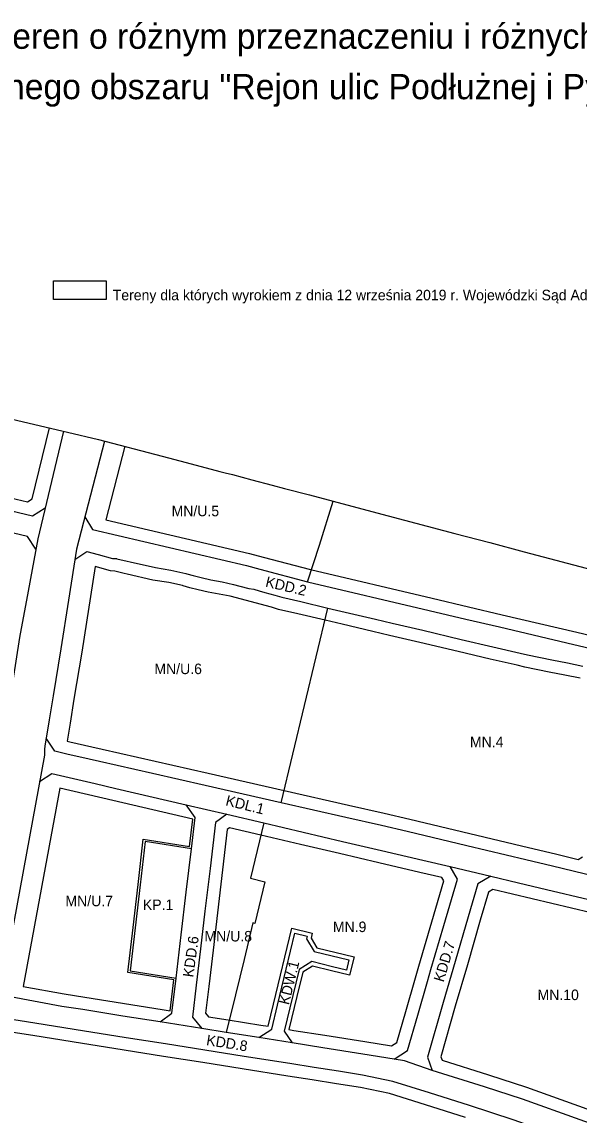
# Model space of a CAD drawing. Extents: x 7416945 to 7418410, y 5548550 to 5549803.
# Drawn here: x 7417613 to 7417879, y 5549282 to 5549803 of the extents above; entities that cross this region are included whole.
import ezdxf

# ---------------------------------------------------------------- set-up
doc = ezdxf.new("R2010")
doc.units = 0
for name, color, linetype in [('_LEGENDA_opisy', 7, 'Continuous'), ('info', 7, 'Continuous'), ('linie rozgraniczające', 7, 'Continuous'), ('nieprzekraczalne linie zabudowy', 7, 'Continuous'), ('obowiazujace linie zabudowy', 7, 'Continuous'), ('przeznaczenia terenów', 7, 'Continuous'), ('wyrok sądu', 7, 'Continuous')]:
    doc.layers.add(name, color=color, linetype=linetype)

msp = doc.modelspace()

# ---------------------------------------------------------------- linework, layer by layer
at = {"layer": 'linie rozgraniczające'}
for points in [[(7417590.76, 5549617.84), (7417614.12, 5549612.32), (7417635.08, 5549607.36), (7417649.74, 5549603.95), (7417680.13, 5549595.95), (7417691.64, 5549592.93), (7417707.71, 5549588.7), (7417710.12, 5549588.07), (7417713.61, 5549587.15), (7417718.26, 5549585.93), (7417722.94, 5549584.69), (7417732.53, 5549582.17), (7417738.47, 5549580.61), (7417750.37, 5549577.48), (7417761.66, 5549574.53), (7417782.44, 5549569.02), (7417819.55, 5549559.17), (7417836.24, 5549554.75), (7417852.72, 5549550.37), (7417888.31, 5549540.93)], [(7417619.99, 5549551.6), (7417616.03, 5549557.7), (7417598.58, 5549561.83), (7417597.44, 5549562.11), (7417575.89, 5549566.8), (7417573.85, 5549567.3), (7417560.72, 5549570.46), (7417545.86, 5549574.04), (7417545.19, 5549574.21), (7417538.59, 5549575.77), (7417490.83, 5549587.31), (7417457.88, 5549595), (7417445.43, 5549597.84), (7417449.35, 5549610.27)], [(7417624.4, 5549571.14), (7417618.37, 5549567.42), (7417600.92, 5549571.55), (7417599.7, 5549571.85), (7417578.14, 5549576.54), (7417576.21, 5549577.02), (7417563.06, 5549580.18), (7417548.26, 5549583.75), (7417547.57, 5549583.92), (7417540.91, 5549585.5), (7417493.14, 5549597.04), (7417461.13, 5549604.52), (7417462.02, 5549607.14), (7417449.35, 5549610.27)], [(7417633.2, 5549607.8), (7417620.9, 5549556.55), (7417616.31, 5549531.69), (7417612.22, 5549509.52), (7417608.98, 5549489.09), (7417604.95, 5549463.66), (7417603.56, 5549458.92), (7417602.9, 5549456.68), (7417600.38, 5549448.11)], [(7417652.74, 5549603.16), (7417639.38, 5549551.6), (7417635.56, 5549527.28), (7417631.94, 5549504.23), (7417628.25, 5549481.74), (7417626.38, 5549470.4), (7417624.29, 5549457.71), (7417624.07, 5549456.36), (7417624.04, 5549453.54), (7417603.72, 5549342.84), (7417602.77, 5549338.52), (7417599.85, 5549325.25), (7417588.8, 5549282.89), (7417582.37, 5549257.96)], [(7417749.47, 5549536.13), (7417755.05, 5549553.61), (7417761.66, 5549574.53)], [(7417643.37, 5549567), (7417646.98, 5549561.01), (7417720.34, 5549543.79), (7417726.77, 5549542.1), (7417749.34, 5549536.16), (7417749.47, 5549536.13), (7417807.39, 5549522.48), (7417824.82, 5549518.37), (7417840.84, 5549514.6), (7417876.37, 5549506.27), (7417906.25, 5549499.17)], [(7417638.6, 5549546.65), (7417644.26, 5549550.46), (7417649.73, 5549549.18), (7417656.46, 5549547.23), (7417658.4, 5549547.16), (7417658.59, 5549547.12), (7417663.48, 5549545.97), (7417664.88, 5549545.65), (7417676.93, 5549542.84), (7417684.36, 5549541.59), (7417691.39, 5549540.13), (7417691.91, 5549539.95), (7417694.87, 5549539.08), (7417698.73, 5549538.09), (7417703.28, 5549537.05), (7417708.67, 5549536.04), (7417714.16, 5549534.74), (7417717.21, 5549534.01), (7417721.4, 5549532.94), (7417723.87, 5549532.52), (7417726.45, 5549531.79), (7417729.02, 5549531.07), (7417731.46, 5549530.42), (7417733.91, 5549529.78), (7417737.21, 5549528.77), (7417746.22, 5549526.65), (7417759.16, 5549523.61), (7417767.29, 5549521.69), (7417781.87, 5549518.26), (7417789.8, 5549516.4), (7417804.3, 5549512.99), (7417822.59, 5549508.68), (7417837.75, 5549505.15), (7417850.7, 5549502.15), (7417854.27, 5549501.33), (7417865.79, 5549498.98), (7417873.31, 5549497.54), (7417880.65, 5549495.98)], [(7417736.94, 5549430.77), (7417759.16, 5549523.61)], [(7417886.55, 5549395.7), (7417866.12, 5549400.6), (7417853.4, 5549403.64), (7417825.31, 5549410.36), (7417796.84, 5549417.18), (7417784.66, 5549419.94), (7417767.63, 5549423.81), (7417752.29, 5549427.29), (7417736.94, 5549430.77), (7417718.83, 5549434.88), (7417700.71, 5549439), (7417675.49, 5549444.73), (7417650.26, 5549450.45), (7417645.37, 5549451.55), (7417634.72, 5549453.96), (7417629.06, 5549455.36), (7417624.93, 5549461.54)], [(7417621.74, 5549441), (7417627.52, 5549444.78), (7417648.26, 5549439.96), (7417658.02, 5549437.69), (7417691.54, 5549429.86), (7417711.02, 5549425.31), (7417728.62, 5549421.18), (7417747.38, 5549416.79), (7417766.07, 5549412.42), (7417784.71, 5549408.05), (7417804.36, 5549403.44), (7417817.37, 5549400.4), (7417836.85, 5549395.83), (7417849.98, 5549392.72), (7417863.34, 5549389.56), (7417883.55, 5549384.77)], [(7417679.25, 5549326.39), (7417684.78, 5549330.63), (7417686.77, 5549347.32), (7417689.2, 5549367.82), (7417691.63, 5549388.3), (7417694.06, 5549408.82), (7417695.82, 5549423.75), (7417691.54, 5549429.86)], [(7417711.02, 5549425.31), (7417705.56, 5549421.48), (7417702.97, 5549399.52), (7417700.56, 5549379.11), (7417698.45, 5549361.26), (7417696.41, 5549343.93), (7417694.62, 5549328.73), (7417699, 5549323.26)], [(7417728.62, 5549421.18), (7417722.23, 5549394.82), (7417729.13, 5549393.15), (7417724.31, 5549373.33), (7417723.37, 5549373.56), (7417719.15, 5549356.21), (7417715.05, 5549339.34), (7417710.69, 5549321.4)], [(7417694.06, 5549408.82), (7417672.04, 5549412.3), (7417669.65, 5549391.79), (7417667.25, 5549371.29), (7417664.86, 5549350.79), (7417686.77, 5549347.32)], [(7417790.77, 5549308.7), (7417797.1, 5549312.71), (7417801.98, 5549329.67), (7417806.61, 5549345.69), (7417808.24, 5549351.31), (7417814.4, 5549372.4), (7417820.84, 5549394.47), (7417817.37, 5549400.4)], [(7417836.85, 5549395.83), (7417830.58, 5549392.17), (7417825.95, 5549376.51), (7417819.85, 5549355.24), (7417814.04, 5549335.58), (7417806.6, 5549309.62), (7417808.87, 5549303.3)], [(7417726.22, 5549318.94), (7417732.34, 5549323.02), (7417735.11, 5549334.46), (7417743.43, 5549368.67), (7417749.27, 5549367.25), (7417748.97, 5549366.02), (7417752.64, 5549359.97), (7417769.16, 5549355.96), (7417767.98, 5549351.1), (7417761.36, 5549352.71), (7417751.46, 5549355.11), (7417745.41, 5549351.43), (7417742.38, 5549338.95), (7417738.28, 5549322.07), (7417742.03, 5549316.43)], [(7417906.81, 5549269.9), (7417851.87, 5549289.57), (7417833.76, 5549295.49), (7417808.87, 5549303.3), (7417795.71, 5549307.92), (7417790.77, 5549308.7), (7417775.81, 5549311.08), (7417756.77, 5549314.1), (7417742.03, 5549316.43), (7417726.22, 5549318.94), (7417710.69, 5549321.4), (7417699, 5549323.26), (7417679.25, 5549326.39), (7417661.44, 5549329.21), (7417642.3, 5549332.24), (7417632.4, 5549333.81), (7417607.94, 5549338.37), (7417603.72, 5549342.84)], [(7418147.34, 5549179.74), (7418143.99, 5549186.16), (7418084.45, 5549204.38), (7418040.68, 5549217.77), (7417983.92, 5549235), (7417952.55, 5549244.38), (7417903.8, 5549259.73), (7417872.26, 5549271.01), (7417847.4, 5549279.75), (7417826.56, 5549286.64), (7417807.47, 5549292.63), (7417790.03, 5549298.09), (7417775.67, 5549301.04), (7417764.12, 5549302.87), (7417752.53, 5549304.72), (7417740.93, 5549306.55), (7417719.26, 5549309.98), (7417700.5, 5549312.94), (7417681.74, 5549315.91), (7417662.97, 5549318.89), (7417638.22, 5549322.81), (7417619.42, 5549325.79), (7417605.57, 5549327.98), (7417599.85, 5549325.25)]]:
    msp.add_lwpolyline(points, dxfattribs=at)
at = {"layer": 'nieprzekraczalne linie zabudowy'}
for points in [[(7417463.05, 5549610.23), (7417494.53, 5549602.88), (7417542.31, 5549591.33), (7417549, 5549589.75), (7417549.7, 5549589.57), (7417564.47, 5549586.02), (7417577.63, 5549582.85), (7417579.5, 5549582.39), (7417601.05, 5549577.7), (7417602.33, 5549577.38), (7417615.96, 5549574.16), (7417618.27, 5549575.58), (7417626.39, 5549609.41)], [(7417662.42, 5549600.65), (7417653.36, 5549565.68), (7417721.79, 5549549.61), (7417728.3, 5549547.9), (7417750.79, 5549541.98), (7417808.77, 5549528.32), (7417826.2, 5549524.21), (7417842.21, 5549520.44), (7417877.75, 5549512.11), (7417907.63, 5549505.01), (7417914.74, 5549503.33), (7417927.56, 5549500.31), (7417941.75, 5549496.96), (7417966.98, 5549491.01), (7417986.45, 5549486.41), (7417997.3, 5549483.85), (7418019.43, 5549478.63), (7418030.21, 5549476.09), (7418048.27, 5549471.83), (7418065.94, 5549467.69), (7418082.97, 5549463.69), (7418104, 5549458.1)], [(7417879.28, 5549490.14), (7417872.12, 5549491.66), (7417864.63, 5549493.09), (7417853, 5549495.47), (7417849.35, 5549496.3), (7417836.39, 5549499.31), (7417821.22, 5549502.84), (7417802.93, 5549507.15), (7417788.43, 5549510.56), (7417780.5, 5549512.42), (7417765.91, 5549515.85), (7417757.78, 5549517.77), (7417744.85, 5549520.81), (7417735.64, 5549522.97), (7417732.27, 5549524.01), (7417712.56, 5549529.21), (7417702.06, 5549531.17), (7417697.32, 5549532.26), (7417693.28, 5549533.29), (7417690.08, 5549534.23), (7417689.79, 5549534.33), (7417683.25, 5549535.69), (7417675.75, 5549536.95), (7417663.53, 5549539.8), (7417662.12, 5549540.13), (7417657.62, 5549541.18), (7417655.5, 5549541.26), (7417648.21, 5549543.37), (7417641.81, 5549502.64), (7417638.12, 5549480.12), (7417636.25, 5549468.77), (7417634.83, 5549460.11), (7417636.11, 5549459.79), (7417646.69, 5549457.4), (7417651.58, 5549456.3), (7417702.04, 5549444.85)], [(7417702.04, 5549444.85), (7417738.27, 5549436.62), (7417768.96, 5549429.66), (7417785.99, 5549425.79), (7417798.2, 5549423.02), (7417826.71, 5549416.2), (7417854.8, 5549409.48), (7417867.52, 5549406.44), (7417878.32, 5549403.84), (7417880.5, 5549405.1)], [(7417694.72, 5549422.96), (7417656.66, 5549431.85), (7417631.31, 5549437.74), (7417613.98, 5549343.35), (7417633.42, 5549339.72), (7417643.24, 5549338.17), (7417680.19, 5549332.32), (7417683.9, 5549331.73)], [(7417740.5, 5549322.75), (7417742.97, 5549322.36), (7417757.71, 5549320.03), (7417776.75, 5549317.01), (7417789.47, 5549314.98), (7417791.96, 5549316.56), (7417796.21, 5549331.33), (7417800.85, 5549347.36), (7417802.48, 5549352.99), (7417808.64, 5549374.08), (7417814.36, 5549393.67), (7417813.49, 5549395.14), (7417802.99, 5549397.6), (7417783.34, 5549402.21), (7417764.7, 5549406.58), (7417746.01, 5549410.95), (7417727.25, 5549415.34), (7417712.27, 5549418.85), (7417711.2, 5549418.11), (7417708.93, 5549398.82), (7417706.52, 5549378.41), (7417704.41, 5549360.56), (7417702.37, 5549343.23), (7417700.87, 5549330.52), (7417702.23, 5549328.82), (7417711.63, 5549327.33), (7417727.16, 5549324.87), (7417730.6, 5549324.32), (7417733.17, 5549334.93), (7417741.96, 5549371.09), (7417751.69, 5549368.72), (7417751.11, 5549366.35), (7417753.92, 5549361.72), (7417771.58, 5549357.43), (7417769.45, 5549348.68), (7417760.89, 5549350.77), (7417751.79, 5549352.97), (7417747.16, 5549350.15), (7417744.32, 5549338.48), (7417740.5, 5549322.75)], [(7417949.72, 5549262.5), (7417978.32, 5549356.16), (7417837.8, 5549389.44), (7417835.66, 5549388.19), (7417831.71, 5549374.83), (7417825.61, 5549353.56), (7417819.8, 5549333.9), (7417812.9, 5549309.83), (7417813.51, 5549308.13), (7417835.59, 5549301.2), (7417853.81, 5549295.25), (7417907.36, 5549276.08), (7417908.75, 5549275.58), (7417931.37, 5549268.24), (7417939.84, 5549265.43), (7417949.72, 5549262.5)], [(7417824.72, 5549280.93), (7417805.68, 5549286.9), (7417788.53, 5549292.27), (7417774.6, 5549295.14), (7417763.18, 5549296.94), (7417751.59, 5549298.79), (7417739.99, 5549300.62), (7417718.32, 5549304.05), (7417699.56, 5549307.01), (7417680.8, 5549309.98), (7417662.03, 5549312.96), (7417637.28, 5549316.88), (7417618.48, 5549319.86), (7417609.16, 5549321.34), (7417598.48, 5549280.38)]]:
    msp.add_lwpolyline(points, dxfattribs=at)
at = {"layer": 'obowiazujace linie zabudowy'}
for points in [[(7417685.66, 5549346.48), (7417663.76, 5549349.95), (7417666.26, 5549371.41), (7417668.66, 5549391.91), (7417671.17, 5549413.45), (7417693.19, 5549409.97), (7417694.72, 5549422.96)], [(7417683.9, 5549331.73), (7417685.66, 5549346.48)]]:
    msp.add_lwpolyline(points, dxfattribs=at)
at = {"layer": 'wyrok sądu'}
msp.add_lwpolyline([(7417628.35, 5549679.55), (7417653.4, 5549679.55), (7417653.4, 5549670.53), (7417628.35, 5549670.53)], close=True, dxfattribs=at)

# ---------------------------------------------------------------- texts
at = {"layer": '_LEGENDA_opisy'}
msp.add_text('Tereny dla których wyrokiem z dnia 12 września 2019 r. Wojewódzki Sąd Administracyjny w Krakowie (sygn. akt II SA/Kr 401/19) stwierdziłnieważność. Prawomocne od dnia 18 maja 2023 r.', height=5, dxfattribs=at).set_placement((7417656.59, 5549670.23))
at = {"layer": 'info'}
for s, p in [('Materiał pomocniczy zawierający linie rozgraniczające teren o różnym przeznaczeniu i różnych warunkach zagospodarowania terenu, ', (7417215.4, 5549790.04)), ('opracowane w skali 1:1000 pochodzące z Miejscowego Planu Zagospodarowania Przestrzennego obszaru "Rejon ulic Podłużnej i Pylnej" zatwierdzonego uchwałą RMK Nr VII/120/19 z dnia 13 lutego 2019 r.', (7416943.86, 5549766.04))]:
    msp.add_text(s, height=12, dxfattribs=at).set_placement(p)
at = {"layer": 'przeznaczenia terenów'}
for s, p in [('MN/U.5', (7417684.64, 5549567.33)), ('MN/U.6', (7417676.44, 5549492.12)), ('MN.4', (7417826.82, 5549457.3)), ('MN/U.7', (7417634.05, 5549381.53)), ('KP.1', (7417670.97, 5549379.71)), ('MN.9', (7417761.5, 5549369.21)), ('MN/U.8', (7417700.31, 5549364.74)), ('MN.10', (7417859.03, 5549336.81))]:
    msp.add_text(s, height=5, dxfattribs=at).set_placement(p)
for s, rotation, p in [('KDD.2', 346.6025, (7417729.06, 5549533.89)), ('KDL.1', 346.19, (7417710.08, 5549429.67)), ('KDD.6', 82.101, (7417694.95, 5549347.44)), ('KDD.7', 73.3618, (7417814.23, 5549345.08)), ('KDW.1', 76.1784, (7417740.52, 5549334.25)), ('KDD.8', 350.9093, (7417700.95, 5549315.42))]:
    msp.add_text(s, height=5, rotation=rotation, dxfattribs=at).set_placement(p)

doc.saveas('drawing.dxf')
